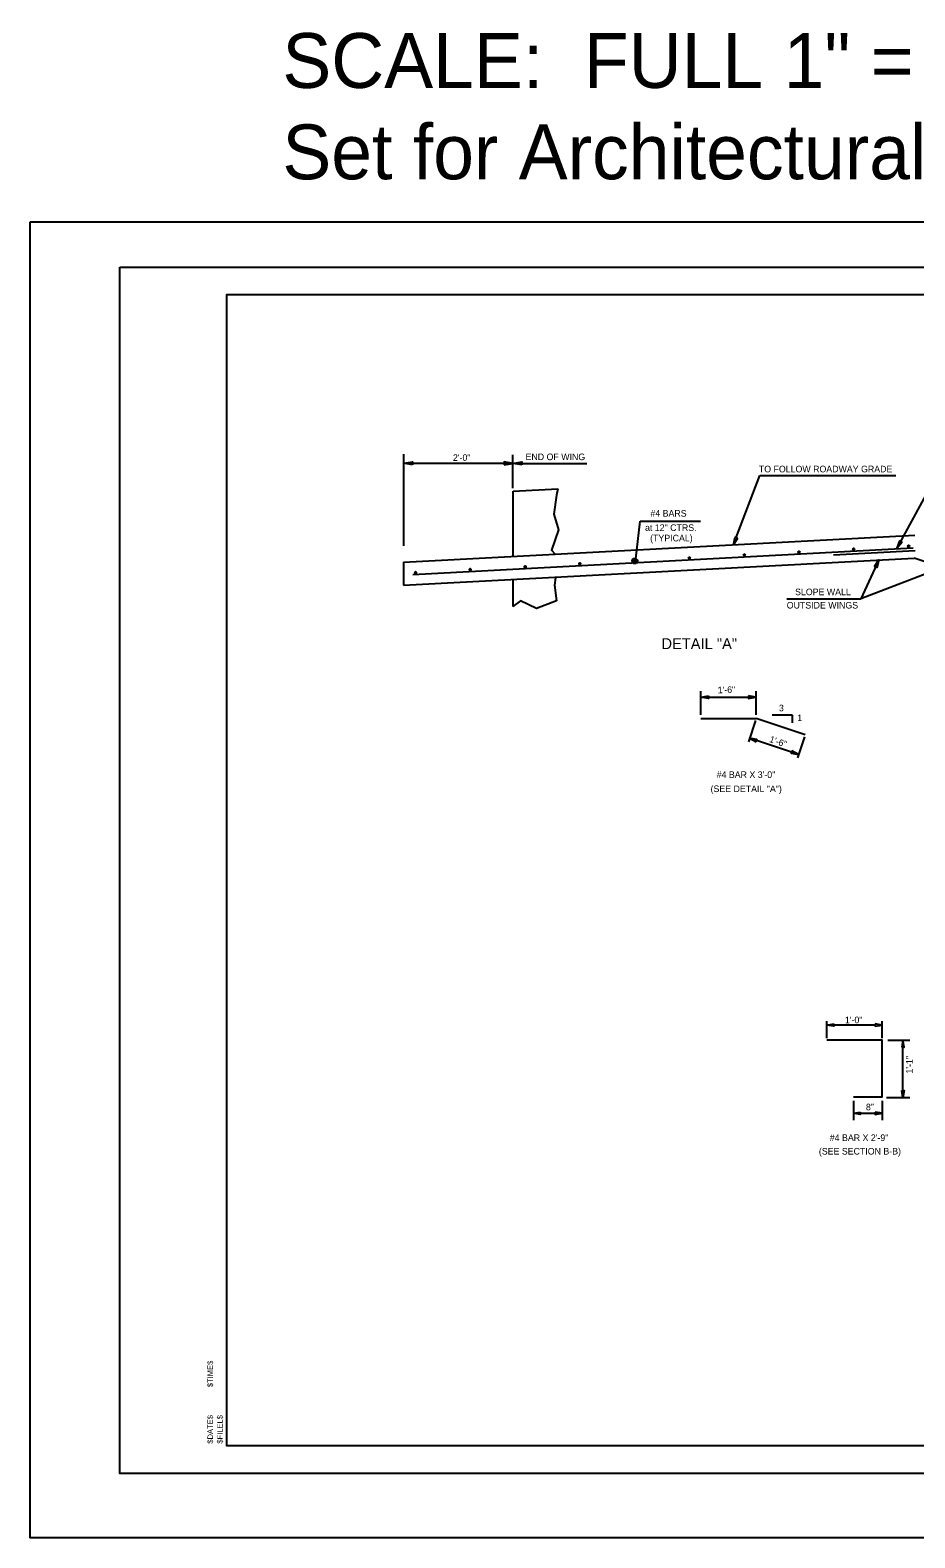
# Model space of a CAD drawing. Extents: x 570 to 2152770, y 726 to 139926.
# Drawn here: x 2151638.73 to 2151654.86, y 139318.2 to 139345.69 of the extents above; entities that cross this region are included whole.
import ezdxf

# ---------------------------------------------------------------- set-up
doc = ezdxf.new("R2010")
doc.units = 0
for name, color, linetype in [('4', 7, 'Continuous'), ('9', 7, 'Continuous'), ('Default', 7, 'Continuous'), ('PR_Bridge', 7, 'Continuous'), ('PR_Dimensions', 7, 'Continuous'), ('PR_Reinforcing', 7, 'Continuous'), ('PR_SlopeWall', 7, 'Continuous'), ('S', 7, 'Continuous'), ('SHT_Plot_Shape_Full', 7, 'Continuous'), ('SHT_Plot_Shape_Half', 7, 'Continuous'), ('SHT_Plot_Stamp', 7, 'Continuous'), ('SHT_Sheet_Border', 7, 'Continuous'), ('SHT_Standard_Sheet_Txt', 7, 'Continuous'), ('T', 7, 'Continuous'), ('T-Title', 7, 'Continuous')]:
    doc.layers.add(name, color=color, linetype=linetype)

# ---------------------------------------------------------------- blocks, each defined once
blk = doc.blocks.new('Stamp_Plot_Stamp')
at = {"layer": 'SHT_Plot_Stamp'}
for s, p in [('$TIME$', (1.695, 1.572)), ('$DATE$', (1.695, 0.542)), ('$FILEL$', (1.873, 0.542))]:
    blk.add_text(s, height=0.1, rotation=90, dxfattribs=at).set_placement(p)
blk = doc.blocks.new('ARROWHD_15')
at = {"layer": 'Default'}
blk.add_lwpolyline([(0.0261, -0.0045), (0.0261, 0.0043), (-0.0004, -0.0001)], close=True, dxfattribs=at)

msp = doc.modelspace()

# ---------------------------------------------------------------- linework, layer by layer
at = {"layer": '4'}
for p in [(2151650.958, 139333.139), (2151652.861, 139332.842)]:
    msp.add_line(p, (2151651.967, 139333.139), dxfattribs=at)
msp.add_lwpolyline([(2151653.742, 139326.238), (2151654.264, 139326.238), (2151654.264, 139327.27), (2151653.259, 139327.27)], dxfattribs=at)
at = {"layer": '9'}
for start, end in [(5.1193, 185.1193), (185.1193, 5.1193)]:
    msp.add_arc((2151654.747, 139336.282), 0.0143, start, end, dxfattribs=at)
at = {"layer": 'PR_Bridge'}
for p, q in [((2151647.532, 139337.283), (2151647.532, 139336.095)), ((2151647.535, 139337.283), (2151648.352, 139337.327)), ((2151647.532, 139335.678), (2151647.532, 139335.184))]:
    msp.add_line(p, q, dxfattribs=at)
at = {"layer": 'PR_Dimensions'}
for p, q in [((2151645.54, 139336.29), (2151645.54, 139337.958)), ((2151647.532, 139337.341), (2151647.532, 139337.949)), ((2151645.654, 139337.793), (2151647.479, 139337.793)), ((2151647.644, 139337.791), (2151648.878, 139337.791)), ((2151652.035, 139337.569), (2151654.513, 139337.569)), ((2151649.851, 139336.74), (2151650.955, 139336.74)), ((2151652.526, 139335.321), (2151653.878, 139335.321)), ((2151650.958, 139333.207), (2151650.958, 139333.636)), ((2151650.958, 139333.528), (2151651.967, 139333.528)), ((2151651.967, 139333.207), (2151651.967, 139333.636)), ((2151652.258, 139333.208), (2151652.624, 139333.208)), ((2151652.624, 139333.208), (2151652.624, 139333.063)), ((2151651.954, 139333.1), (2151651.826, 139332.716)), ((2151652.741, 139332.482), (2151651.847, 139332.78)), ((2151652.848, 139332.802), (2151652.72, 139332.419)), ((2151653.259, 139327.309), (2151653.259, 139327.62)), ((2151654.138, 139327.548), (2151653.259, 139327.548)), ((2151654.264, 139327.309), (2151654.264, 139327.62)), ((2151654.368, 139327.27), (2151654.769, 139327.27)), ((2151654.644, 139326.28), (2151654.644, 139327.236)), ((2151653.742, 139326.165), (2151653.742, 139325.814)), ((2151654.264, 139326.165), (2151654.264, 139325.814)), ((2151654.346, 139326.228), (2151654.769, 139326.228)), ((2151653.742, 139325.94), (2151654.264, 139325.94))]:
    msp.add_line(p, q, dxfattribs=at)
for points in [[(2151645.702, 139337.766), (2151645.542, 139337.793), (2151645.702, 139337.819)], [(2151647.373, 139337.765), (2151647.533, 139337.792), (2151647.373, 139337.818)], [(2151647.692, 139337.765), (2151647.532, 139337.791), (2151647.692, 139337.818)], [(2151651.627, 139336.431), (2151651.556, 139336.308), (2151651.584, 139336.447)], [(2151654.629, 139336.356), (2151654.541, 139336.244), (2151654.587, 139336.378)], [(2151654.125, 139335.914), (2151654.205, 139336.032), (2151654.167, 139335.895)], [(2151651.097, 139333.55), (2151651.097, 139333.505), (2151650.962, 139333.528)], [(2151651.829, 139333.55), (2151651.829, 139333.505), (2151651.963, 139333.528)], [(2151653.384, 139327.569), (2151653.384, 139327.527), (2151653.259, 139327.548)], [(2151654.138, 139327.569), (2151654.138, 139327.527), (2151654.264, 139327.548)], [(2151654.623, 139327.145), (2151654.665, 139327.145), (2151654.644, 139327.27)], [(2151654.623, 139326.354), (2151654.665, 139326.354), (2151654.644, 139326.228)], [(2151653.867, 139325.96), (2151653.867, 139325.919), (2151653.742, 139325.94)], [(2151654.138, 139325.96), (2151654.138, 139325.919), (2151654.264, 139325.94)]]:
    msp.add_lwpolyline(points, close=True, dxfattribs=at)
for points in [[(2151651.605, 139336.439), (2151652.035, 139337.569)], [(2151648.352, 139337.327), (2151648.329, 139337.213), (2151648.28, 139336.866), (2151648.363, 139336.583), (2151648.238, 139336.211), (2151648.299, 139336.136)], [(2151654.541, 139336.244), (2151655.111, 139337.298)], [(2151649.773, 139336.054), (2151649.851, 139336.74)], [(2151654.205, 139336.032), (2151653.878, 139335.321)], [(2151655.366, 139335.894), (2151653.878, 139335.321)], [(2151648.306, 139335.707), (2151648.29, 139335.573), (2151648.328, 139335.287), (2151647.962, 139335.144), (2151647.667, 139335.288), (2151647.532, 139335.184)]]:
    msp.add_lwpolyline(points, dxfattribs=at)
msp.add_circle((2151649.754, 139336.012), 0.0479, dxfattribs=at)
at = {"layer": 'PR_Reinforcing'}
for p, q in [((2151645.705, 139335.765), (2151654.83, 139336.249)), ((2151653.38, 139336.125), (2151654.87, 139336.204))]:
    msp.add_line(p, q, dxfattribs=at)
for centre in [(2151652.75, 139336.173), (2151653.746, 139336.224), (2151654.747, 139336.283), (2151647.755, 139335.905), (2151648.751, 139335.961), (2151649.754, 139336.012), (2151650.75, 139336.065), (2151651.752, 139336.12), (2151645.756, 139335.799), (2151646.752, 139335.855)]:
    msp.add_circle(centre, 0.0143, dxfattribs=at)
for centre, start, end in [((2151652.749, 139336.173), 5.1193, 185.1193), ((2151652.749, 139336.173), 185.1193, 5.1193), ((2151653.746, 139336.225), 5.1193, 185.1193), ((2151653.746, 139336.225), 185.1193, 5.1193), ((2151647.755, 139335.906), 5.1193, 185.1193), ((2151647.755, 139335.906), 185.1193, 5.1193), ((2151648.751, 139335.961), 5.1193, 185.1193), ((2151648.751, 139335.961), 185.1193, 5.1193), ((2151649.754, 139336.012), 5.1193, 185.1193), ((2151649.754, 139336.012), 185.1193, 5.1193), ((2151650.75, 139336.065), 5.1193, 185.1193), ((2151650.75, 139336.065), 185.1193, 5.1193), ((2151651.752, 139336.12), 5.1193, 185.1193), ((2151651.752, 139336.12), 185.1193, 5.1193), ((2151645.756, 139335.799), 5.1193, 185.1193), ((2151645.756, 139335.799), 185.1193, 5.1193), ((2151646.752, 139335.855), 5.1193, 185.1193), ((2151646.752, 139335.855), 185.1193, 5.1193)]:
    msp.add_arc(centre, 0.0143, start, end, dxfattribs=at)
at = {"layer": 'PR_SlopeWall'}
for p, q in [((2151645.539, 139335.989), (2151654.86, 139336.483)), ((2151645.537, 139335.572), (2151654.852, 139336.066)), ((2151645.539, 139335.989), (2151645.539, 139335.573)), ((2151654.85, 139336.067), (2151656.793, 139335.419))]:
    msp.add_line(p, q, dxfattribs=at)
at = {"layer": 'SHT_Plot_Shape_Full'}
msp.add_lwpolyline([(2151638.727, 139342.197), (2151674.727, 139342.197), (2151674.727, 139318.197), (2151638.727, 139318.197)], close=True, dxfattribs=at)
at = {"layer": 'SHT_Plot_Shape_Half'}
msp.add_lwpolyline([(2151640.365, 139341.372), (2151674.365, 139341.372), (2151674.365, 139319.372), (2151640.365, 139319.372)], close=True, dxfattribs=at)
at = {"layer": 'SHT_Sheet_Border'}
msp.add_lwpolyline([(2151673.815, 139319.872), (2151642.315, 139319.872), (2151642.315, 139340.872), (2151673.815, 139340.872)], close=True, dxfattribs=at)

# ---------------------------------------------------------------- block references
at = {"layer": 'PR_Dimensions'}
for p, xscale, yscale, rotation in [((2151651.847, 139332.78), 5.094669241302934, 5.094669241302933, -18.4257938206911), ((2151652.739, 139332.483), 5.094669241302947, 5.094669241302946, 161.57420617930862)]:
    msp.add_blockref('ARROWHD_15', p, dxfattribs=dict(at, xscale=xscale, yscale=yscale, rotation=rotation))
at = {"layer": 'SHT_Standard_Sheet_Txt'}
msp.add_blockref('Stamp_Plot_Stamp', (2151640.365, 139319.372), dxfattribs=at)

# ---------------------------------------------------------------- texts
at = {"layer": 'S'}
for s, p in [('SCALE:  FULL 1" = 1\'-0" (SF=12) HALF 1/2 " = 1\'-0"', (2151643.327, 139344.639)), ('Set for Architectural Units', (2151643.327, 139342.973))]:
    msp.add_text(s, height=1.00003, dxfattribs=at).set_placement(p)
at = {"layer": 'T'}
for s, p in [('2\'-0"', (2151646.438, 139337.838)), ('END OF WING', (2151647.762, 139337.851)), ('TO FOLLOW ROADWAY GRADE', (2151652.017, 139337.629)), ('#4 BARS', (2151650.039, 139336.821)), ('at 12" CTRS.', (2151649.941, 139336.56)), ('(TYPICAL)', (2151650.034, 139336.37)), ('SLOPE WALL', (2151652.677, 139335.388)), ('OUTSIDE WINGS', (2151652.525, 139335.145)), ('3', (2151652.383, 139333.271)), ('1', (2151652.716, 139333.091)), ('#4 BAR X 3\'-0"', (2151651.247, 139332.055)), ('(SEE DETAIL "A")', (2151651.136, 139331.797)), ('1\'-0"', (2151653.586, 139327.582)), ('8"', (2151653.969, 139325.994)), ('#4 BAR X 2\'-9"', (2151653.31, 139325.434)), ('(SEE SECTION B-B)', (2151653.111, 139325.187))]:
    msp.add_text(s, height=0.12, dxfattribs=at).set_placement(p)
for s, rotation, p in [('1\'-6"', 1.5677, (2151651.267, 139333.599)), ('1\'-6"', 340.8033, (2151652.198, 139332.713)), ('1\'-1"', 90, (2151654.822, 139326.664))]:
    msp.add_text(s, height=0.12, rotation=rotation, dxfattribs=at).set_placement(p)
at = {"layer": 'T-Title'}
msp.add_text('DETAIL "A"', height=0.2, dxfattribs=at).set_placement((2151650.24, 139334.404))

doc.saveas('drawing.dxf')
